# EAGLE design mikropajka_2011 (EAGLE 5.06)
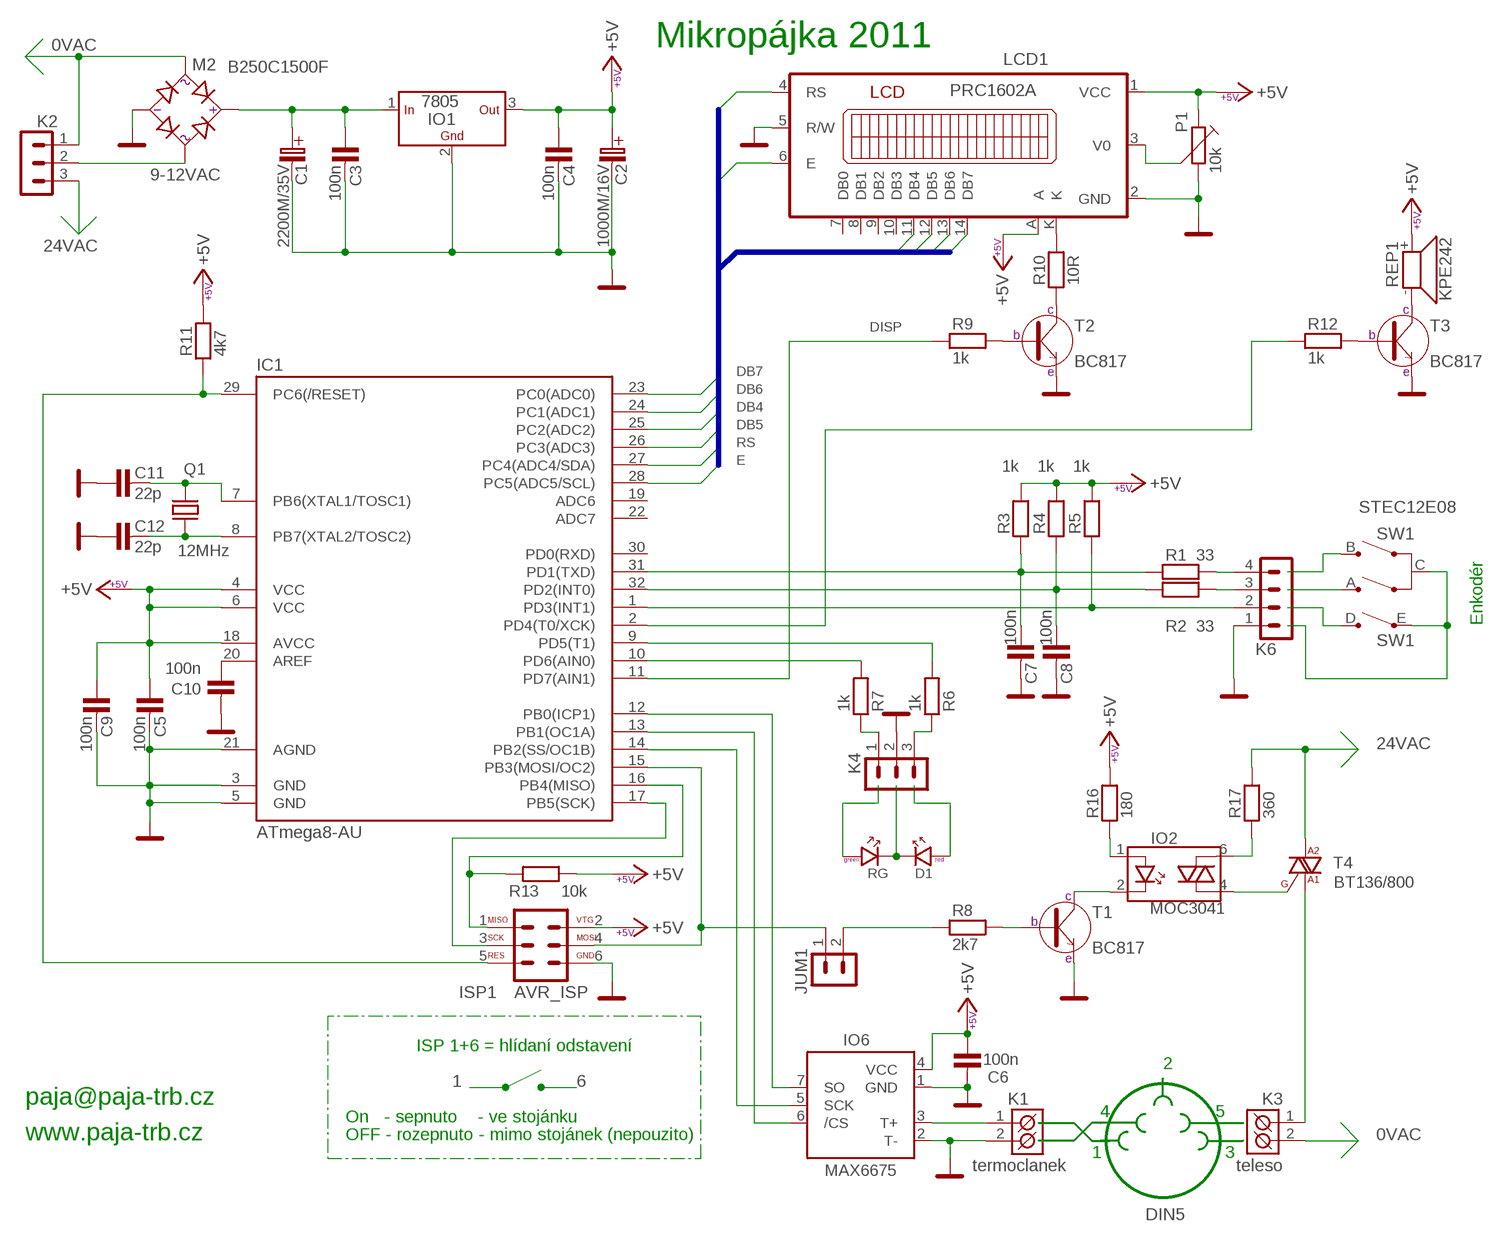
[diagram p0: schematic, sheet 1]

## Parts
C1  2200M/35V  [C_EL_7,5]
C2  1000M/16V  [C_EL_5]
C3  100n  C-KERAMIK_SMD_1206  [1206]
C4  100n  C-KERAMIK_SMD_1206  [1206]
C5  100n  C-KERAMIK_SMD_1206  [1206]
C6  100n  C-KERAMIK_SMD_1206  [1206]
C7  100n  C-KERAMIK_SMD_1206  [1206]
C8  100n  C-KERAMIK_SMD_1206  [1206]
C9  100n  C-KERAMIK_SMD_0805  [0805]
C10  100n  C-KERAMIK_SMD_0805  [0805]
C11  22p  C-KERAMIK_SMD_1206  [1206]
C12  22p  C-KERAMIK_SMD_1206  [1206]
D1  RG  LED_DUO_5  [LED_5-DUO]
IC1  ATmega8-AU  ATMEGA8-AU  [TQFP32-08]
IO1  7805  78_STOJ_STOJ  [TO-220S]
IO2  MOC3041  MOC3020  [DIL6]
IO6  MAX6675  [SO08]
ISP1  AVR_ISP  [MLW06G]
JUM1  S1G2_JUMP  [S1G2_JUM]
K1  termoclanek  ARK500/2  [ARK500/2]
K2  PSH04-03P  [PSH04-03P]
K3  teleso  ARK500/2  [ARK500/2]
K4  PSH02-03P  [PSH02-03P]
K6  PSH02-04P  [PSH02-04P]
LCD1  PRC1602A  [PRC1602A]
M2  B250C1500F  D-MUSTEK_B250C4000  [DM_KBL]
P1  10k  TRIMRPT6H  [PT6H]
Q1  12MHz  Q_HC-49U  [HC-49U]
R1  33  R_SMD_0805  [0805]
R2  33  R_SMD_0805  [0805]
R3  1k  R_7,5  [R-7,5]
R4  1k  R_7,5  [R-7,5]
R5  1k  R_10  [R-10]
R6  1k  R_SMD_1206  [1206]
R7  1k  R_SMD_1206  [1206]
R8  2k7  R_SMD_1206  [1206]
R9  1k  R_SMD_1206  [1206]
R10  10R  R_SMD_1206  [1206]
R11  4k7  R_SMD_1206  [1206]
R12  1k  R_SMD_1206  [1206]
R13  10k  R_SMD_1206  [1206]
R16  180  R_SMD_1206  [1206]
R17  360  R_SMD_1206  [1206]
REP1  KPE242  [KPE242]
SW1  STEC12E08  KODER_ROTACNIEC12  [EC12]
T1  BC817  [SOT-23]
T2  BC817  [SOT-23]
T3  BC817  [SOT-23]
T4  BT136/800  BT136_STOJ  [TO-220S]

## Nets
0VAC: K2.1 K3.2(K2) M2.AC1
9-12VAC: K2.2 M2.AC2
24VAC: K2.3 R17.2 T4.2(A2)
+5V: C2.C+(C_EL+) C4.1 C5.1 C6.1 C9.1 IC1.4(VCC) IC1.6(VCC) IC1.18(AVCC) IO1.3(OUT) IO6.4(VCC) ISP1.2 LCD1.1(VCC) LCD1.A P1.1 R3.2 R4.2 R5.2 R11.2 R13.2 R16.2 REP1.+
A: SW1.A(A:A)
B: SW1.B(A:B)
B$3: IC1.17(PB5(SCK)) ISP1.3
D: SW1.D(B:D)
DB4: IC1.25(PC2(ADC2)) LCD1.11(DB4)
DB5: IC1.26(PC3(ADC3)) LCD1.12(DB5)
DB6: IC1.24(PC1(ADC1)) LCD1.13(DB6)
DB7: IC1.23(PC0(ADC0)) LCD1.14(DB7)
DISP: IC1.11(PD7(AIN1)) R9.1
E: IC1.28(PC5(ADC5/SCL)) LCD1.6(E)
GND: C1.C-(C_EL-) C2.C-(C_EL-) C3.2 C4.2 C5.2 C6.2 C7.2 C8.2 C9.2 C10.2 C11.1 C12.1 IC1.3(GND) IC1.5(GND) IC1.21(AGND) IO1.2(GND) IO6.1(GND) IO6.2(T-) ISP1.6 K1.2(K2) K4.2 K6.1 LCD1.2(GND) LCD1.5(R/W) M2.- P1.2 T1.2(E) T2.2(E) T3.2(E)
GND1: D1.K SW1.C(A:C) SW1.E(B:E)
GREEN: D1.A2
N$1: IC1.9(PD5(T1)) R6.2
N$2: C11.2 IC1.7(PB6(XTAL1/TOSC1)) Q1.2
N$3: IC1.10(PD6(AIN0)) R7.2
N$4: C12.2 IC1.8(PB7(XTAL2/TOSC2)) Q1.1
N$5: IC1.14(PB2(SS/OC1B)) IO6.5(SCK)
N$6: IO6.3(T+) K1.1(K1)
N$7: IC1.13(PB1(OC1A)) IO6.6(/CS)
N$8: IO2.2(K) T1.3(C)
N$9: K4.3 R6.1
N$10: K4.1 R7.1
N$11: IC1.29(PC6(/RESET)) ISP1.5 R11.1
N$12: IO2.4 T4.3(G)
N$13: IC1.12(PB0(ICP1)) IO6.7(SO)
N$14: R8.2 T1.1(B)
N$15: C7.1 IC1.31(PD1(TXD)) R1.1 R3.1
N$16: C8.1 IC1.32(PD2(INT0)) R2.1 R4.1
N$17: IC1.1(PD3(INT1)) K6.2 R5.1
N$18: IO2.6 R17.1
N$19: IO2.1(A) R16.1
N$20: LCD1.K R10.2
N$21: K3.1(K1) T4.1(A1)
N$22: JUM1.2 R8.1
N$23: C1.C+(C_EL+) C3.1 IO1.1(IN) M2.+
N$24: IC1.16(PB4(MISO)) ISP1.1 R13.1
N$25: IC1.15(PB3(MOSI/OC2)) ISP1.4 JUM1.1
N$26: REP1.- T3.3(C)
N$27: R10.1 T2.3(C)
N$32: R12.2 T3.1(B)
N$33: IC1.2(PD4(T0/XCK)) R12.1
N$34: R9.2 T2.1(B)
N$35: K6.4 R1.2
N$36: K6.3 R2.2
N$38: C10.1 IC1.20(AREF)
RED: D1.A1
RS: IC1.27(PC4(ADC4/SDA)) LCD1.4(RS)
VO: LCD1.3(V0) P1.3
Unconnected: IC1.19(ADC6) IC1.22(ADC7) IC1.30(PD0(RXD)) LCD1.7(DB0) LCD1.8(DB1) LCD1.9(DB2) LCD1.10(DB3)

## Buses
SBERNICE_LCD

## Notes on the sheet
- Mikropájka 2011
- Enkodér
- ISP 1+6 = hlídaní odstavení
- 2
- paja@paja-trb.cz | 4 | 5
- On   - sepnuto    - ve stojánku
- www.paja-trb.cz | OFF - rozepnuto - mimo stojánek (nepouzito)
- 1 | 3
- DIN5

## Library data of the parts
C1 = #PaJa_C-el_2:2200M/35V
C2 = #PaJa_C-el_2:1000M/16V
C3-C12 = #PaJa_22:C-KERAMIK: Kondenzator - keramicky
D1 = #PaJa_22:LED_DUO: LED dioda - dvoubarevna - 3 vyvody, spol. Katoda
IC1 = atmega8:ATMEGA8
IO1 = #PaJa_31:78??: Stabilizátor - 1A a 1,5A ?? - napeti => 05, 06, 08, 09, 12, 15, 18, 20, 24 => 1,5A ?? - napeti => 10, 12, 15, 18 => 1A S ?? - napeti => 05, 09, 10, 12, 15, 18, 24 => 2A T ?? - napeti => 05 => 3A
IO2 = #PAJA_92:MOC3020
IO6 = #PaJa_31:MAX6675: Cold Junction compensated K-Thermocouple to digital converter (0°C to + 1024°C)
ISP1 = #PaJa_31:AVR_ISP: AVR ISP konektor (dle standardu)
JUM1 = #PaJa_konektory:S1G2_JUMP: Radove konektory - koliky - 2x
K1 K3 = #PaJa_konektory:ARK500/2: Svorkovnice - roztec 5mm - dvojita
K2 = #PaJa_konektory:PSH04-03: Konektory se zamkem - vidlice - 3pin, RM3,96mm
K4 = #PaJa_konektory:PSH02-03: Konektory se zamkem - vidlice - 3pin
K6 = #PaJa_konektory:PSH02-04: Konektory se zamkem - vidlice - 4pin
LCD1 = #PaJa_displeje:PRC1602A: LCD - 2x16 + LED (TME - LCM1602ASL) LCD Anzeige TC1602E(L) http://www.lcd-module.de/deu/pdf/doma/dip162-d.pdf
M2 = #PaJa_31:D-MUSTEK: Diodovy mustek - Graetz
P1 = #PaJa_31:TRIMR: Trimr
Q1 = #PaJa_22:Q_HC-49U: Krystal - 1MHz - 48MHz
R1 R2 R9 R10 R12 = #PaJa_22:R: Rezistor
R3-R5 R11 = #PaJa_31:R: Rezistor
R6 R7 = #PaJa_ostatni:R: Rezistor
R8 R13 R16 R17 = #PaJa_23_e56:R: Rezistor
REP1 = #PaJa_31:KPE242: Piezo-sirenka - 70dB - 3V az 16V
SW1 = #PaJa_22:KODER_ROTACNI: Rotacni koder se spinacem v hrideli www.tme.cz
T1 = #PaJa_30:BC817: SMD tranzistor - NPN - ekv. BC337
T2 T3 = #PaJa_22:BC817: SMD tranzistor - NPN - ekv. BC337
T4 = #PaJa_23_e56:BT136: Triac - 600V, 4A

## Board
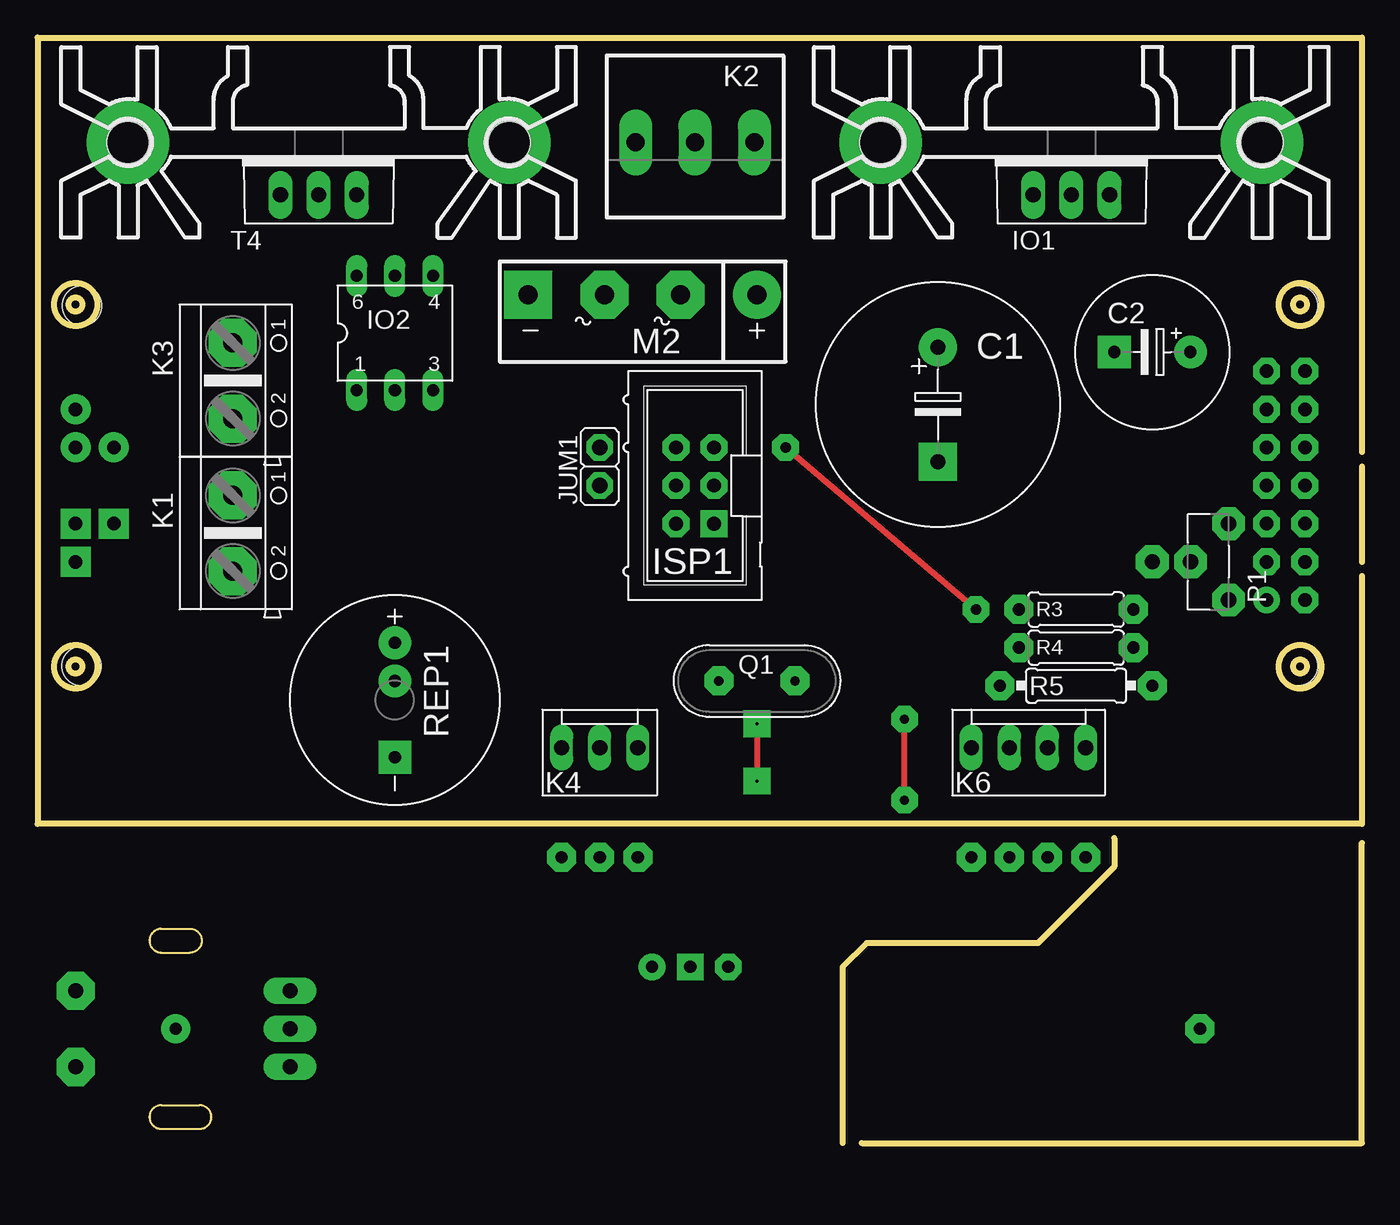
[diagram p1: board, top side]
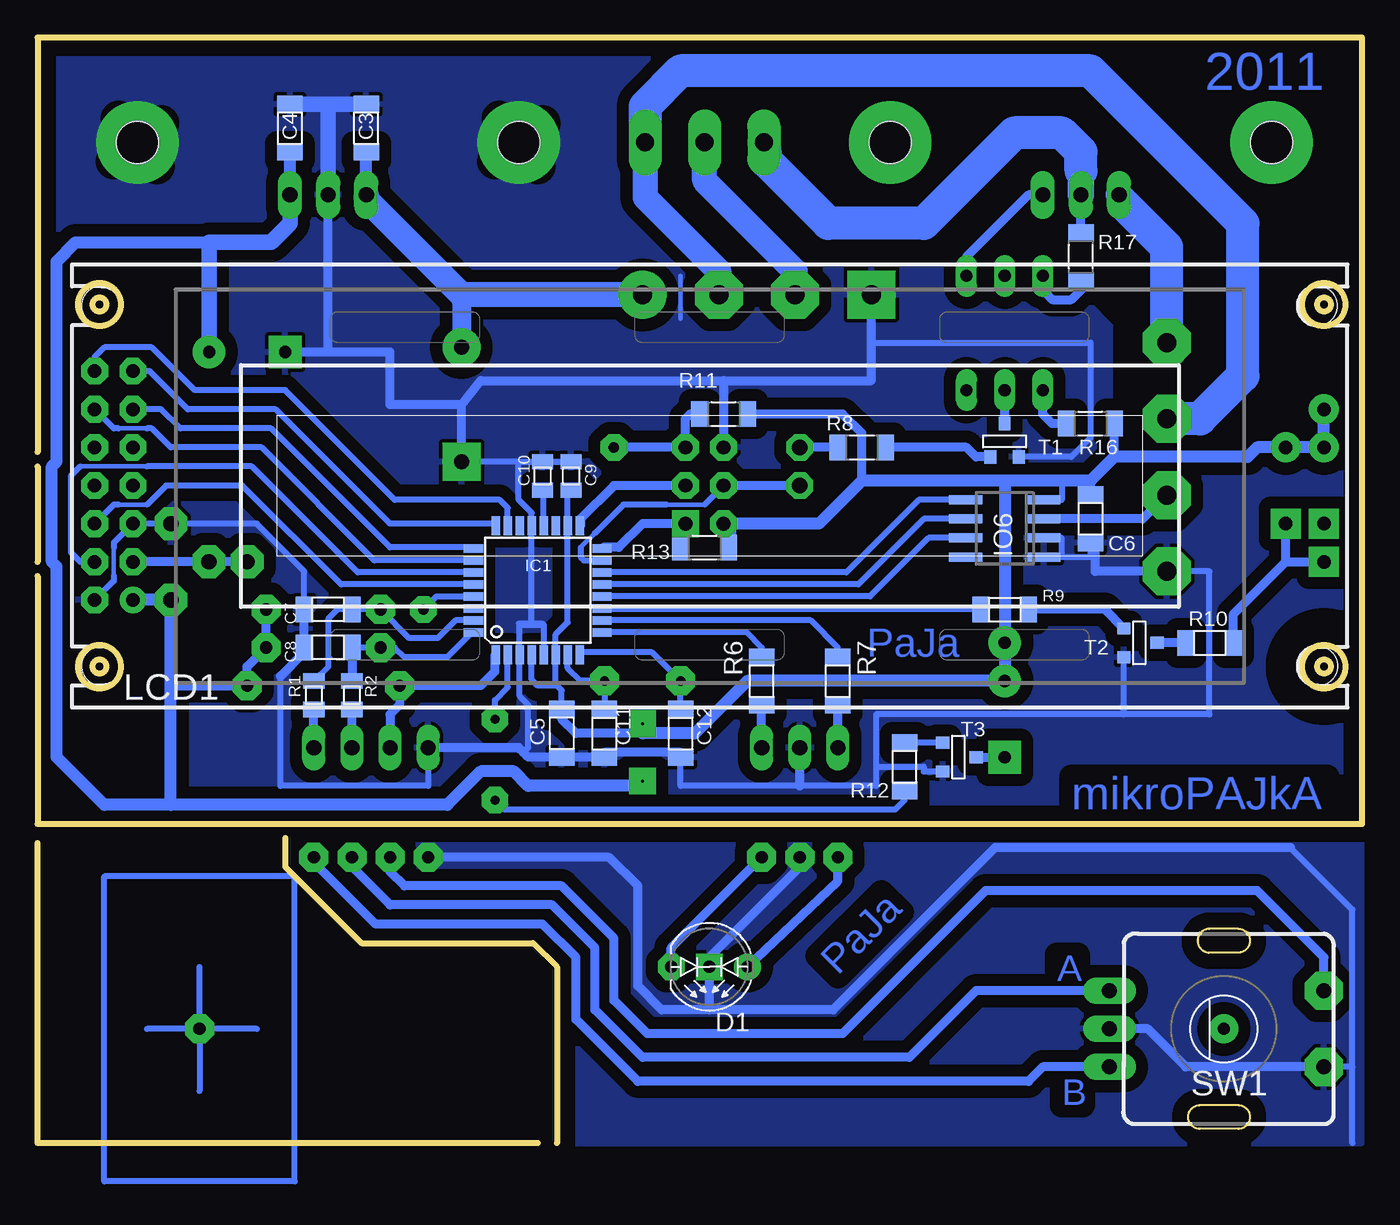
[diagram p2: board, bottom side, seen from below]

Size 88.27 x 73.66 mm. Coordinates in mm from the lower left corner, seen from the top.
Outline: 71.76,20.32 71.76,18.42 66.68,13.33 55.24,13.33 53.66,11.75 53.66,0
Outline: 88.27,46.04 88.27,73.66 0,73.66 0,21.27 88.27,21.27 88.27,37.78
Outline: 88.27,45.09 88.27,38.73
Outline: 54.93,0 88.27,0 88.27,20
Outline: circle at 84.14,55.88 radius 1.42
Outline: circle at 84.14,55.88 radius 0.45
Outline: circle at 84.14,31.75 radius 1.42
Outline: circle at 84.14,31.75 radius 0.45
Outline: circle at 2.54,55.88 radius 1.42
Outline: circle at 2.54,55.88 radius 0.45
Outline: circle at 2.54,31.75 radius 1.42
Outline: circle at 2.54,31.75 radius 0.45
Copper layers (1*16): Top 0.035mm / dielectric 1.5mm / Bottom 0.035mm
Design rules "default": minimum track width 10mil, minimum drill 24mil, track to track 8mil, track to pad 8mil, pad to pad 8mil, via to via 8mil, smd to smd 8mil, copper to edge 40mil, drill to drill 8mil, minimum pad ring 10mil, minimum via ring 8mil, stop-mask expansion 4mil, vias tented up to drill 0mil, thermal gap 10mil
bRestrict: area 81.3,53 to 87,58.7; area 81.3,28.9 to 87,34.6; area -0.3,53 to 5.4,58.7; area -0.3,28.9 to 5.4,34.6; 7 lines

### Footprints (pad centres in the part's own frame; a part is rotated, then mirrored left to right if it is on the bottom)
C_EL_7,5 = drill 1.016 pad 2.54 round: C+ -3.81,0 | drill 1.016 pad 2.54 square: C- 3.81,0
C_EL_5 = drill 0.813 pad 2.184 round: C+ -2.54,0 | drill 0.813 pad 2.184 square: C- 2.54,0
1206 = smd 1.143 x 1.702: 1 -1.587,0; 2 1.587,0
0805 = smd 1.016 x 1.422: 1 -0.953,0; 2 0.953,0
LED_5-DUO = drill 0.813 pad 1.778 octagon: A1 2.54,0 | drill 0.813 pad 1.778 round: A2 -2.54,0 | drill 0.813 pad 1.778 square: K 0,0
TQFP32-08 = smd 1.27 x 0.559: 1 -4.293,2.8; 2 -4.293,2; 3 -4.293,1.2; 4 -4.293,0.4; 5 -4.293,-0.4; 6 -4.293,-1.2; 7 -4.293,-2; 8 -4.293,-2.8; 17 4.293,-2.8; 18 4.293,-2; 19 4.293,-1.2; 20 4.293,-0.4; 21 4.293,0.4; 22 4.293,1.2; 23 4.293,2; 24 4.293,2.8 | smd 0.559 x 1.27: 9 -2.8,-4.293; 10 -2,-4.293; 11 -1.2,-4.293; 12 -0.4,-4.293; 13 0.4,-4.293; 14 1.2,-4.293; 15 2,-4.293; 16 2.8,-4.293; 25 2.8,4.293; 26 2,4.293; 27 1.2,4.293; 28 0.4,4.293; 29 -0.4,4.293; 30 -1.2,4.293; 31 -2,4.293; 32 -2.8,4.293
TO-220S = drill 1.016 pad 1.6 long: 1 -2.54,0; 2 0,0; 3 2.54,0
DIL6 = drill 0.813 pad 1.4 long: 1 -2.54,-3.81; 2 0,-3.81; 3 2.54,-3.81; 4 2.54,3.81; 5 0,3.81; 6 -2.54,3.81
SO08 = smd 0.6 x 2.2: 1 -1.905,-2.6; 2 -0.635,-2.6; 3 0.635,-2.6; 4 1.905,-2.6; 5 1.905,2.6; 6 0.635,2.6; 7 -0.635,2.6; 8 -1.905,2.6
MLW06G = drill 0.914 pad 1.778 square: 1 -2.54,-1.27 | drill 0.914 pad 1.778 octagon: 2 -2.54,1.27; 3 0,-1.27; 4 0,1.27; 5 2.54,-1.27; 6 2.54,1.27
S1G2_JUM = drill 1.016 pad 1.778 octagon: 1 -1.27,0; 2 1.27,0
ARK500/2 = drill 1.27 pad 3.2 octagon: 1 -2.54,0; 2 2.54,0
PSH04-03P = drill 1.2 pad 2.184 long: 1 -3.962,0; 2 0,0; 3 3.962,0
PSH02-03P = drill 1.016 pad 1.422 long: 1 -2.54,0; 2 0,0; 3 2.54,0
PSH02-04P = drill 1.016 pad 1.422 long: 1 -3.81,0; 2 -1.27,0; 3 1.27,0; 4 3.81,0
PRC1602A = drill 0.9 pad 1.778 round: 1 -38.1,-7.62 | drill 0.9 pad 1.778 octagon: 2 -40.64,-7.62; 3 -38.1,-5.08; 4 -40.64,-5.08; 5 -38.1,-2.54; 6 -40.64,-2.54; 7 -38.1,0; 8 -40.64,0; 9 -38.1,2.54; 10 -40.64,2.54; 11 -38.1,5.08; 12 -40.64,5.08; 13 -38.1,7.62; 14 -40.64,7.62 | drill 0.9 pad 2 round: A 41.275,5.08; A1 41.275,2.54; A2 38.735,2.54 | drill 0.9 pad 2 square: K 41.275,-5.08; K1 41.275,-2.54; K2 38.735,-2.54 | hole 2.6: -40.172,11.976; -40.172,-12.026; 40.871,-12.026; 40.84,11.976
DM_KBL = drill 1.27 pad 3.2 round: + -7.62,0 | drill 1.27 pad 3.2 square: - 7.62,0 | drill 1.27 pad 3.2 octagon: AC1 -2.54,0; AC2 2.54,0
PT6H = drill 1.016 pad 2.184 octagon: 1 -2.54,-1.27; 2 2.54,-1.27; 3 0,1.27
HC-49U = drill 0.61 pad 1.93 octagon: 1 -2.54,0; 2 2.54,0
R-7,5 = drill 0.813 pad 1.93 octagon: 1 -3.81,0; 2 3.81,0
R-10 = drill 0.813 pad 1.93 octagon: 1 -5.08,0; 2 5.08,0
KPE242 = drill 0.813 pad 2.184 round: + -3.81,0 | drill 0.813 pad 2.184 square: - 3.81,0
EC12 = drill 1 pad 1.778 long: A -2.54,-7.62; B 2.54,-7.62; C 0,-7.62 | drill 1 pad 2.54 octagon: D -2.54,6.668; E 2.54,6.668
SOT-23 = smd 0.787 x 0.889: 1 -0.953,-0.953; 2 0.953,-0.953; 3 0,1.27
CH_HS-135A = hole 2.8: -12.7,0; 12.7,0

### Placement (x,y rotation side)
C1  60.01,49.21 270 top
C2  74.3,52.7 180 top
C3  66.36,67.63 90 bottom
C4  71.44,67.63 90 bottom
C5  53.34,27.31 270 bottom
C6  18.1,41.59 270 bottom
C7  68.9,35.56 180 bottom
C8  68.9,33.02 180 bottom
C9  52.7,44.45 90 bottom
C10  54.61,44.45 90 bottom
C11  50.48,27.31 90 bottom
C12  45.4,27.31 90 bottom
D1  43.5,11.75 180 bottom
IC1  54.93,36.83 90 bottom
IO1  68.9,63.18 0 top
IO2  23.81,53.98 0 top
IO6  23.81,40.96 90 bottom
ISP1  43.81,43.81 90 top
JUM1  37.46,45.09 90 top
K1  13.02,40.64 270 top
K2  43.81,66.68 180 top
K3  13.02,50.8 270 top
K4  37.46,26.35 0 top
K6  66.04,26.35 0 top
LCD1  43.81,43.81 0 bottom
M2  40.32,56.52 180 top
P1  78.11,38.73 90 top
Q1  47.94,30.8 0 top
R1  69.85,29.85 270 bottom
R2  67.31,29.85 270 bottom
R3  69.22,35.56 0 top
R4  69.22,33.02 0 top
R5  69.22,30.48 0 top
R6  40,30.8 90 bottom
R7  34.92,30.8 90 bottom
R8  33.34,46.35 0 bottom
R9  23.81,35.56 0 bottom
R10  10.16,33.34 0 bottom
R11  42.54,48.58 0 bottom
R12  30.48,25.08 90 bottom
R13  43.81,39.69 0 bottom
R16  18.1,47.94 0 bottom
R17  18.73,59.05 90 bottom
REP1  23.81,29.53 270 top
SW1  9.21,7.62 270 bottom
T1  23.81,46.67 0 bottom
T2  14.92,33.34 270 bottom
T3  26.99,25.72 270 bottom
T4  18.73,63.18 0 top
U$1  [CH_HS-135A]  18.73,66.68 0 top
U$4  [CH_HS-135A]  68.9,66.68 0 top

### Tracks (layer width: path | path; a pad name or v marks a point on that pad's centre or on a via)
0VAC
  Bottom 1.676: K2.1 47.78,63.02 42.86,58.1 M2.AC1
  Bottom 2.184: K3.2 10.79,48.26 7.94,51.12 7.94,61.28 18.1,71.44 45.4,71.44 47.78,69.06 K2.1
9-12VAC
  Bottom 1.676: K2.2 43.81,64.14 37.78,58.1 M2.AC2
24VAC
  Bottom 0.61: R17.2 T4.2
  Bottom 1.778: T4.2 18.73,64.77
  Bottom 2.184: K2.3 39.69,65.41 35.56,61.28 29.21,61.28 23.18,67.31 20,67.31 18.73,66.04 18.73,64.77
+5V  (via drill 0.2 pad 1.78, 0.81 pad 2.18)
  Top 0.406: v47.94,27.94 v47.94,24.13
  Bottom 0.406: 20,44.13 20,42.86 IO6.4 | 53.73,30.48 53.66,30.48 53.34,30.16 C5.1 | 53.73,32.45 53.66,32.38 | 55.24,32.45 IC1.4 55.33,30.88 54.93,30.48 53.73,30.48 | 47.94,27.31 v47.94,27.94 | R13.2 41.91,39.69 41.91,41.27 | 53.73,30.48 53.73,32.45 | C9.1 52.93,43.27 IC1.18 52.93,34.7 53.73,33.9 IC1.6 53.73,32.45
  Bottom 0.61: R11.2 34.61,48.58 33.34,47.31 33.34,44.13 | 18.1,44.13 C6.1 | C5.1 53.34,28.26 52.39,27.31 47.94,27.31 | v47.94,24.13 47.94,23.81 | 41.91,41.27 ISP1.2 | 16.51,45.72 R16.2 | R3.2 R4.2 74.3,31.75 R5.2 79.38,30.48
  Bottom 0.813: IO1.3 C4.1 | 23.81,44.13 20,44.13 18.1,44.13 16.51,45.72 7.62,45.72 6.98,46.35 2.54,46.35 LCD1.A | 23.81,44.13 33.34,44.13 36.2,41.27 41.91,41.27 | 76.84,60.01 85.73,60.01 87,58.74 87,45.4 87.31,45.09 87.31,38.73 87,38.42 87,25.72 83.82,22.54 79.38,22.54 | 47.94,23.81 55.56,23.81 56.52,24.77 58.74,24.77 60.96,22.54 79.38,22.54 | 47.94,27.31 44.45,27.31 40.96,30.8 v23.81,30.8 REP1.+ 23.81,44.13 | 79.38,22.54 79.38,30.48 P1.1 LCD1.1
  Bottom 1.016: IO1.3 71.44,61.28 72.71,60.01 76.84,60.01 C2.C+
A  (via drill 0.81 pad 1.93)
  Bottom 0.61: v67.31,19.05 67.31,18.42 64.77,15.88 53.98,15.88 51.12,13.02 51.12,8.89 47.94,5.71 30.16,5.71 25.72,10.16 SW1.A
B  (via drill 0.81 pad 1.93)
  Bottom 0.61: v69.85,19.05 69.85,18.73 65.72,14.61 54.61,14.61 52.39,12.38 52.39,8.26 48.26,4.13 22.23,4.13 21.27,5.08 SW1.B
B$3
  Bottom 0.406: 52.07,41.18 IC1.17
  Bottom 0.61: ISP1.3 49.85,43.81 52.07,41.59 52.07,41.18
D  (via drill 0.81 pad 1.93)
  Bottom 0.61: v64.77,19.05 64.77,18.1 63.82,17.15 53.34,17.15 49.85,13.65 49.85,9.53 47.62,7.3 34.61,7.3 25.08,16.83 6.98,16.83 2.54,12.38 SW1.D
DB4
  Bottom 0.406: LCD1.11 80.01,48.89 78.74,47.62 72.71,47.62 64.77,39.69 59.37,39.69 59,39.63 IC1.25
DB5
  Bottom 0.305: 80.96,47.62 82.87,47.62
  Bottom 0.406: LCD1.12 83.19,47.62 82.87,47.62 | 80.96,47.62 80.65,47.62 79.38,46.35 73.34,46.35 65.82,38.83 IC1.26
DB6
  Bottom 0.406: LCD1.13 80.8,51.43 78.26,48.89 72.39,48.89 64.77,41.27 57.88,41.27 IC1.24
DB7
  Bottom 0.406: LCD1.14 84.45,52.39 83.82,53.02 80.65,53.02 77.79,50.16 71.76,50.16 64.45,42.86 57.47,42.86 56.93,42.32 IC1.23
DISP
  Bottom 0.406: IC1.11 50.56,35.56 R9.1
E
  Bottom 0.305: 80.96,42.54 82.87,42.54
  Bottom 0.406: 80.96,42.54 79.69,43.81 74.61,43.81 68.03,37.23 IC1.28 | 82.87,42.54 83.19,42.54 LCD1.6
GND  (via drill 2.8 pad 5.5)
  Bottom 0.305: 83.19,39.69 83.19,37.78 | 45.4,54.93 45.4,57.78
  Bottom 0.406: LCD1.2 83.19,37.46 83.19,37.78 | 83.19,39.69 83.19,40 LCD1.5 P1.2 73.66,41.27 70.48,38.1 C7.2 | IO6.2 20,40.32 20,39.05 | 54.53,34.52 IC1.5 | 54.53,34.52 54.61,34.61 55.24,34.61 | 55.24,34.61 55.33,34.69 | 55.24,34.61 55.88,34.61 | 55.88,34.61 56.2,34.61 | 20,39.05 IO6.1 | C6.2 18.1,39.05 20,39.05 | 70.48,32.7 C8.2 | 72.07,31.12 72.07,23.81 62.23,23.81 K6.1 | K1.2 10.16,38.1 10.16,28.58 15.88,28.58 | 15.88,28.58 T2.2 | T1.2 19.37,45.72 18.1,46.99 18.1,53.34 32.7,53.34 | C12.1 45.4,23.81 37.46,23.81 32.38,23.81 32.38,25.08 | 32.38,25.08 29.21,25.08 29.21,24.77 T3.2 | 32.38,25.08 32.38,28.58 15.88,28.58 | 56.2,45.4 56.2,42.86 55.33,41.99 IC1.21 55.33,34.61 55.88,34.61 | 56.2,45.4 C10.2 C9.2 | 56.2,45.4 C1.C- | 55.88,26.04 55.56,26.35 55.56,29.21 56.13,29.78 IC1.3 56.13,34.52 54.53,34.52
  Bottom 0.61: 68.9,52.7 64.77,52.7 64.77,49.21 60.01,49.21 | 68.9,52.7 C2.C- | 68.9,52.7 IO1.2 | C1.C- 60.01,49.21 | 42.54,50.8 32.7,50.8 32.7,53.34 M2.- | 42.54,50.8 58.74,50.8 60.01,49.21 | 42.54,50.8 ISP1.6 | C8.2 C7.2 | 72.07,31.12 70.48,32.7 | 37.46,23.81 K4.2 | C12.1 45.4,26.04 50.48,26.04 C11.1 C5.2 55.56,25.72 55.88,26.04 56.2,26.35 K6.1 | 17.78,39.69 17.78,38.1 K1.2
  Bottom 1.016: 68.9,69.22 C3.2 | 68.9,69.22 C4.2 | IO1.2 68.9,69.22
  other vias: 56.2,66.68 81.6,66.68
  pour Bottom (isolate 0.813): 0,73.66 88.27,73.66 88.27,21.27 0,21.27
GND1  (via drill 0.81 pad 1.93)
  Bottom 0.406: 4.76,19.69 0.64,15.56 0.64,5.08 | 0.64,5.08 SW1.E | 0.64,0 0.64,5.08
  Bottom 0.61: v37.46,19.05 37.46,18.42 43.5,12.38 D1.K 43.5,8.89 | 4.76,19.69 24.45,19.69 35.24,8.89 43.5,8.89 | v62.23,19.05 50.16,19.05 48.26,17.15 48.26,10.48 46.67,8.89 43.5,8.89 | SW1.E 11.75,5.08 14.29,7.62 SW1.C
  pour Bottom (isolate 0.813): 0,0 0,21.27 70.8,21.27 70.8,18.1 67.31,14.29 54.93,14.29 52.7,12.06 52.7,0
GREEN  (via drill 0.81 pad 1.93)
  Bottom 0.61: v34.92,19.05 34.92,17.46 D1.A2
N$1
  Bottom 0.406: R6.2 40,33.02 41.02,34.03 IC1.9
N$2
  Bottom 0.406: C11.2 Q1.2 52.07,30.8 52.93,31.66 IC1.7
N$3
  Bottom 0.406: R7.2 34.92,33.02 36.73,34.83 IC1.10
N$4
  Bottom 0.406: IC1.8 52.13,32.44 52.07,32.7 47.31,32.7 Q1.1 C12.2
N$5
  Bottom 0.406: IO6.5 29.53,42.86 34.36,38.03 IC1.14
N$6
  Bottom 0.61: IO6.3 14.61,41.59 K1.1
N$7
  Bottom 0.406: IO6.6 29.21,41.59 33.57,37.23 IC1.13
N$8
  Bottom 0.61: T1.3 IO2.2
N$9
  Bottom 0.61: K4.3 R6.1
N$10
  Bottom 0.61: K4.1 R7.1
N$11  (via drill 0.7 pad 1.78)
  Top 0.406: v49.85,46.35 v62.55,35.56
  Bottom 0.406: v62.55,35.56 61.68,36.43 IC1.29
  Bottom 0.61: v49.85,46.35 ISP1.5 45.09,48.26 44.77,48.58 R11.1
N$12
  Bottom 0.61: T4.3 22.23,63.18 26.35,59.05 IO2.4
N$13
  Bottom 0.406: IO6.7 28.89,40.32 32.78,36.43 IC1.12 50.55,36.51
N$14
  Bottom 0.61: T1.1 25.72,45.72 26.35,46.35 R8.2
N$15
  Bottom 0.406: IC1.31 60.42,34.83 61.59,33.66 63.5,33.66 R3.1 C7.1 68.26,35.56 68.9,34.92 68.9,31.75 R1.1
N$16
  Bottom 0.406: IC1.32 59.31,34.03 60.96,32.38 63.82,32.38 64.45,33.02 R4.1 C8.1
  Bottom 0.61: C8.1 R2.1
N$17
  Bottom 0.406: 57.78,32.48 IC1.1
  Bottom 0.61: K6.2 64.77,28.58 64.14,29.21 R5.1 58.74,30.48 57.78,31.43 57.78,32.48
N$18
  Bottom 0.61: R17.1 18.73,56.83 19.37,56.2 20.64,56.2 21.27,56.83 IO2.6
N$19
  Bottom 0.61: R16.1 20.64,47.94 21.27,48.58 IO2.1
N$20
  Bottom 0.61: 5.08,38.73 LCD1.K | 5.08,38.73 5.08,41.27 | 5.08,38.73 8.57,35.24 R10.2
N$21
  Bottom 1.778: 15.88,62.55 15.88,62.86 T4.1
  Bottom 2.184: K3.1 13.02,59.69 15.88,62.55
N$22
  Bottom 0.61: R8.1 JUM1.2
N$23
  Bottom 0.813: IO1.1 C3.1
  Bottom 1.27: 60.01,56.52 C1.C+
  Bottom 1.676: M2.+ 60.01,56.52 66.04,62.55 66.36,62.86 IO1.1
N$24
  Bottom 0.406: 50.58,39.69 IC1.16 | R13.1 45.72,39.69 45.72,41.27
  Bottom 0.61: ISP1.1 45.72,41.27 47.94,41.27 49.53,39.69 50.58,39.69
N$25
  Bottom 0.305: 43.81,42.54 46.35,42.54 | 51.12,40.64 52.07,39.69
  Bottom 0.406: 46.35,42.54 49.21,42.54 51.12,40.64 | ISP1.4 43.81,42.54 | 52.07,39.69 52.07,39.05 51.85,38.83 IC1.15
  Bottom 0.61: JUM1.1 ISP1.4
N$26
  Bottom 0.61: T3.3 REP1.-
N$27
  Bottom 0.61: R10.1 T2.3
N$28  (via drill 2.8 pad 5.5)
  other vias: 6.03,66.68
N$29  (via drill 2.8 pad 5.5)
  other vias: 31.43,66.68
N$31  (via drill 0.81 pad 1.93)
  Bottom 0.406: v77.47,7.62 77.47,11.75 | v77.47,7.62 77.47,3.49 | 73.66,7.62 v77.47,7.62 | v77.47,7.62 80.96,7.62
N$32
  Bottom 0.406: T3.1 R12.2
N$33  (via drill 0.6 pad 1.78)
  Top 0.406: v57.78,22.86 v57.78,28.26
  Bottom 0.406: R12.1 30.48,22.86 31.12,22.23 57.15,22.23 v57.78,22.86 | IC1.2 56.93,30.39 57.78,29.53 v57.78,28.26
N$34
  Bottom 0.61: R9.2 17.15,35.56 T2.1
N$35
  Bottom 0.61: K6.4 R1.2
N$36
  Bottom 0.61: K6.3 R2.2
N$37
  Bottom 0.406: 71.12,-2.54 71.12,17.78 83.82,17.78 83.82,-2.54 71.12,-2.54
N$38
  Bottom 0.406: C10.1 54.53,43.41 IC1.20
N$46  (via drill 0.81 pad 1.93)
  other vias: 9.21,7.62
RED  (via drill 0.81 pad 1.93)
  Bottom 0.61: v40,19.05 46.04,13.02 D1.A1
RS
  Bottom 0.305: 80.96,45.09 85.41,45.09
  Bottom 0.406: 85.41,45.09 86.04,44.45 86.04,39.37 85.41,38.73 LCD1.4 | 80.96,45.09 73.98,45.09 66.92,38.03 IC1.27
VO  (via drill 1 pad 2.18)
  Bottom 0.61: LCD1.3 P1.3 v74.3,38.73

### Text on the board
Bottom: 2011 | PaJa | mikroPAJkA | A | PaJa | B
